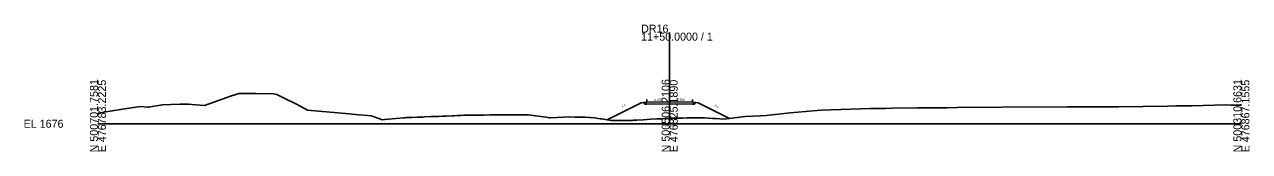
# Model space of a CAD drawing. Extents: x -26 to 403, y -10 to 1535.
# Drawn here: x -25.7 to 402.8, y 1490.3 to 1534.7 of the extents above; entities that cross this region are included whole.
import ezdxf

# ---------------------------------------------------------------- set-up
doc = ezdxf.new("R2010")
doc.units = 0
for name, color, linetype in [('Exist Cross Section Cell', 7, 'Continuous'), ('Exist XS Center Line Elevation Label', 7, 'Continuous'), ('Exist XS Ground Line', 7, 'Continuous'), ('Prop XS Earthwork Shape', 7, 'Continuous'), ('Prop XS EOT Tick Mark', 7, 'Continuous'), ('Prop XS Finish Grade', 7, 'Continuous'), ('Prop XS Finish Grade Earthwork', 7, 'Continuous'), ('Prop XS Finish Grade Pavement', 7, 'Continuous'), ('Prop XS Pvmt Edge Slope', 7, 'Continuous'), ('Prop XS SE Text', 7, 'Continuous'), ('Prop XS Shoulder Borrow Shape', 7, 'Continuous'), ('Prop XS Side Slope Text', 7, 'Continuous'), ('Prop XS Subgrade Earthwork', 7, 'Continuous')]:
    doc.layers.add(name, color=color, linetype=linetype)

msp = doc.modelspace()

# ---------------------------------------------------------------- linework, layer by layer
at = {"layer": 'Exist Cross Section Cell'}
for p, q in [((200, 1500), (200, 1531.85)), ((0, 1500), (200, 1500)), ((200, 1500), (400, 1500))]:
    msp.add_line(p, q, dxfattribs=at)
at = {"layer": 'Exist XS Ground Line'}
msp.add_lwpolyline([(0, 1503.72), (8.64, 1505.07), (14.79, 1506.05), (17.41, 1505.81), (17.84, 1505.8), (18.29, 1505.92), (22.54, 1506.65), (28.65, 1506.83), (31.69, 1506.9), (32.85, 1506.77), (37.29, 1506.4), (46.71, 1509.72), (49.37, 1510.62), (55.18, 1510.59), (61.4, 1510.51), (62.6, 1510.24), (64.93, 1509.05), (69.66, 1506.73), (73.32, 1504.77), (87.88, 1503.42), (91.28, 1503.07), (94.38, 1502.88), (95.58, 1502.81), (98.62, 1501.68), (99.42, 1501.35), (100.41, 1501.46), (101.66, 1501.58), (106.88, 1502.07), (107.46, 1502.1), (107.97, 1502.13), (108.73, 1502.16), (109.85, 1502.21), (111.64, 1502.27), (112, 1502.29), (113.67, 1502.35), (114.25, 1502.37), (116.74, 1502.48), (118.22, 1502.54), (119.22, 1502.58), (120.38, 1502.63), (121.83, 1502.69), (123.95, 1502.77), (124.31, 1502.79), (124.63, 1502.8), (125.63, 1502.85), (126.92, 1502.91), (128.28, 1502.97), (129.66, 1503.01), (130.98, 1503.01), (132.02, 1503.03), (133.03, 1503.04), (134.61, 1503.05), (135.11, 1503.06), (137.19, 1503.08), (137.62, 1503.08), (139.36, 1503.09), (139.73, 1503.09), (141.44, 1503.1), (142.22, 1503.1), (143.5, 1503.11), (144.78, 1503.11), (145.45, 1503.12), (146.96, 1503.13), (147.59, 1503.14), (148.64, 1503.14), (149.73, 1503.15), (150.64, 1503.15), (157.5, 1502.13), (158.01, 1502.05), (158.36, 1502.02), (165.12, 1502.38), (166.81, 1502.32), (170.48, 1502.26), (173.73, 1502.09), (175.7, 1501.77), (176.28, 1501.69), (179.42, 1501.18), (180.45, 1501.16), (180.89, 1501.16), (184.02, 1501.18), (186.3, 1501.15), (186.65, 1501.15), (186.97, 1501.17), (187.4, 1501.2), (188.08, 1501.25), (188.51, 1501.27), (190.85, 1501.41), (191.96, 1501.48), (193.41, 1501.57), (195.66, 1501.67), (195.97, 1501.69), (197.13, 1501.74), (198.53, 1501.81), (199.08, 1501.83), (200, 1501.88), (200.85, 1501.93), (201.89, 1501.95), (203.62, 1501.97), (204.58, 1501.99), (206.17, 1502.02), (206.68, 1502.02), (208.89, 1502.04), (210.61, 1502.05), (211.1, 1502.07), (212.14, 1502.04), (214.94, 1501.87), (216.13, 1501.8), (218.93, 1501.64), (226.41, 1502.52), (231.8, 1502.79), (233.79, 1502.85), (242.16, 1503.8), (252.93, 1504.74), (270.28, 1505.35), (275.43, 1505.31), (277.67, 1505.43), (286.64, 1505.51), (297.05, 1505.62), (300.72, 1505.64), (316.09, 1505.77), (339.13, 1505.89), (340.32, 1505.9), (345.45, 1505.92), (348.48, 1505.93), (357.1, 1505.97), (374.14, 1506.2), (377.12, 1506.22), (380.84, 1506.28), (382.8, 1506.29), (394.43, 1506.57), (396.43, 1506.53), (400, 1506.54)], dxfattribs=at)
at = {"layer": 'Prop XS Earthwork Shape'}
msp.add_lwpolyline([(190, 1507.35), (178.1, 1501.4), (179.42, 1501.18), (180.45, 1501.16), (180.89, 1501.16), (184.02, 1501.18), (186.3, 1501.15), (186.65, 1501.15), (186.97, 1501.17), (187.4, 1501.2), (188.08, 1501.25), (188.51, 1501.27), (190.85, 1501.41), (191.96, 1501.48), (193.41, 1501.57), (195.66, 1501.67), (195.97, 1501.69), (197.13, 1501.74), (198.53, 1501.81), (199.08, 1501.83), (200, 1501.88), (200.85, 1501.93), (201.89, 1501.95), (203.62, 1501.97), (204.58, 1501.99), (206.17, 1502.02), (206.68, 1502.02), (208.89, 1502.04), (210.61, 1502.05), (211.1, 1502.07), (212.14, 1502.04), (214.94, 1501.87), (216.13, 1501.8), (218.93, 1501.64), (220.94, 1501.88), (210, 1507.35), (209.26, 1507.41), (208.68, 1506.83), (208, 1506.84), (200, 1507), (192, 1506.84), (191.32, 1506.83), (190.74, 1507.41)], close=True, dxfattribs=at)
at = {"layer": 'Prop XS EOT Tick Mark'}
for p, q in [((192, 1507.51), (192, 1508.51)), ((208, 1507.51), (208, 1508.51))]:
    msp.add_line(p, q, dxfattribs=at)
at = {"layer": 'Prop XS Finish Grade'}
for p, q in [((192, 1507.51), (190.74, 1507.41)), ((208, 1507.51), (209.26, 1507.41))]:
    msp.add_line(p, q, dxfattribs=at)
at = {"layer": 'Prop XS Finish Grade Earthwork'}
for p, q in [((190, 1507.35), (178.1, 1501.4)), ((190.74, 1507.41), (190, 1507.35)), ((209.26, 1507.41), (210, 1507.35)), ((210, 1507.35), (220.94, 1501.88))]:
    msp.add_line(p, q, dxfattribs=at)
at = {"layer": 'Prop XS Finish Grade Pavement'}
for p, q in [((192, 1507.51), (200, 1507.67)), ((200, 1507.67), (208, 1507.51))]:
    msp.add_line(p, q, dxfattribs=at)
at = {"layer": 'Prop XS Pvmt Edge Slope'}
for p, q in [((192, 1507.51), (191.32, 1506.83)), ((208, 1507.51), (208.68, 1506.83))]:
    msp.add_line(p, q, dxfattribs=at)
at = {"layer": 'Prop XS Shoulder Borrow Shape'}
for points in [[(192, 1507.51), (191.32, 1506.83), (190.74, 1507.41)], [(208.68, 1506.83), (209.26, 1507.41), (208, 1507.51)]]:
    msp.add_lwpolyline(points, close=True, dxfattribs=at)
at = {"layer": 'Prop XS Subgrade Earthwork'}
for p, q in [((191.32, 1506.83), (190.74, 1507.41)), ((192, 1506.84), (191.32, 1506.83)), ((200, 1507), (192, 1506.84)), ((208, 1506.84), (200, 1507)), ((208, 1506.84), (208.68, 1506.83)), ((208.68, 1506.83), (209.26, 1507.41))]:
    msp.add_line(p, q, dxfattribs=at)

# ---------------------------------------------------------------- texts
at = {"layer": 'Exist Cross Section Cell'}
for s, p in [('DR16', (190, 1531.85)), ('11+50.0000 / 1', (190, 1529.05)), ('EL 1676', (-26, 1498.6))]:
    msp.add_text(s, height=2.8, dxfattribs=at).set_placement(p)
for s, p in [('N 500701.7581', (0, 1490)), ('E 476783.2225', (2.8, 1490)), ('N 500506.2106', (200, 1490)), ('E 476825.1890', (202.8, 1490)), ('N 500310.6631', (400, 1490)), ('E 476867.1555', (402.8, 1490))]:
    msp.add_text(s, height=2.8, rotation=90, dxfattribs=at).set_placement(p)
at = {"layer": 'Exist XS Center Line Elevation Label'}
msp.add_text('1677.88', height=0.75, dxfattribs=at).set_placement((198.31, 1499.13))
at = {"layer": 'Prop XS SE Text'}
for rotation, p in [(1.1458, (194.69, 1508.06)), (358.8542, (202.69, 1508.11))]:
    msp.add_text('0.020', height=0.75, rotation=rotation, dxfattribs=at).set_placement(p)
at = {"layer": 'Prop XS Side Slope Text'}
for rotation, p in [(26.5651, (183.38, 1505.71)), (333.4349, (215.61, 1506.22))]:
    msp.add_text('2:1', height=0.75, rotation=rotation, dxfattribs=at).set_placement(p)

doc.saveas('drawing.dxf')
